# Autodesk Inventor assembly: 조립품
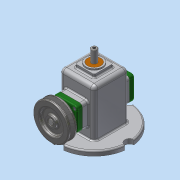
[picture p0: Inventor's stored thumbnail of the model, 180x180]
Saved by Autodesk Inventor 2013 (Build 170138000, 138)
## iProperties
Created: 2018-07
Part Number: 조립품
Document SubType Name: Assembly
Designer: Administrator
Author: Administrator
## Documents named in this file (16)
- C:\Users\Administrator\Desktop\480708V1017\조립품.iam
- C:\Users\Administrator\Desktop\480708V1017\본체.ipt
- C:\Users\Administrator\Desktop\480708V1017\V벨트풀리.ipt
- C:\Users\Administrator\Desktop\480708V1017\고정핀 1.2x8.ipt
- C:\Users\Administrator\Desktop\480708V1017\뒤커버.ipt
- C:\Users\Administrator\Desktop\480708V1017\링크.ipt
- C:\Users\Administrator\Desktop\480708V1017\멈춤나사 M3x8.ipt
- C:\Users\Administrator\Desktop\480708V1017\베어링 12x32x10.ipt
- C:\Users\Administrator\Desktop\480708V1017\볼트 M4.ipt
- C:\Users\Administrator\Desktop\480708V1017\부시.ipt
- C:\Users\Administrator\Desktop\480708V1017\슬라이드.ipt
- C:\Users\Administrator\Desktop\480708V1017\앞커버.ipt
- C:\Users\Administrator\Desktop\480708V1017\오일 실 12 25 7.ipt
- C:\Users\Administrator\Desktop\480708V1017\키 4x4x10.ipt
- C:\Users\Administrator\Desktop\480708V1017\편심축.ipt
- C:\Users\Administrator\Desktop\480708V1017\핀 5x18.ipt
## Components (3 placed, 3 different names)
1. V벨트풀리:1
2. 고정핀 1.2x8:1
3. 핀 5x18:1
